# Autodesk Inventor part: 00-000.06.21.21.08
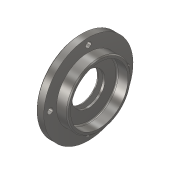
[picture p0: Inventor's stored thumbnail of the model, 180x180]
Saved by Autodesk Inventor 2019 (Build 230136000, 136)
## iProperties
Created: 2019-01
Part Number: 00-000.06.21.21.08
Material: Steel, Mild
Document SubType Name: Modeling
Designer: m.vorobev
Density: 7.85 g/cm^3
Appearance: Semi-Polished
Author: m.vorobev
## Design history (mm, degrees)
sketch "Sketch1"
  geometry: L1 (0, -26)-(12, -26); L2 (12, -26)-(12, -70); L3 (12, -70)-(0, -70); L4 (0, -70)-(0, -26); L5 (12, -50)-(29, -50); L6 (29, -50)-(29, -45); L7 (29, -45)-(12, -45); L8 (12, -45)-(12, -50); L9 (1.413, -26)-(8.5, -26); L10 (8.5, -26)-(7.456, -34.5); L11 (7.456, -34.5)-(2.456, -34.5); L12 (2.456, -34.5)-(1.413, -26); L13 (0, 0)-(11.392, 0); L14 (4.956, -34.5)-(4.956, -26); 1 further point
  constraints: 28 end point, 5 parallel, 4 horizontal, 3 midpoint, 2 perpendicular, 2 point on line, 1 vertical, 1 vertical alignment
  dimensions: "d0" = 140 diameter of L3 L13; "d1" = 100 diameter of L5 L13; "d2" = 90 diameter of L7 L13; "d3" = 52 diameter of L1 L13; "d4" = 5 distance of L10.end L11.end; "d5" = 14 deg angle of L10 L12; "d6" = 69 diameter of L11 L13; "d7" = 3.5 distance of L1.end L9.end; "d8" = 12 distance of L1.start L1.end; "B" = 29 distance between parallel lines of L4 L6
revolve "Revolution1" sketch "Sketch1" stored, may be unused: angle "d10" = 90 deg
fillet "Fillet1" dims "d11" = 2
chamfer "Chamfer1" distance "d12" = 1.5; stored, may be unused: second distance "d13" = 2, angle "d14" = 45 deg
sketch "Sketch2"
  geometry: L1 (0, 0)-(0, -60)
  constraints: 2 end point, 1 vertical
  dimensions: "d15" = 60 distance of L1.start L1.end
hole "Hole1" sketch "Sketch2" at (0, -60) diameter "d16" = 9; stored, may be unused: countersink angle "d20" = 90 deg, drill point angle "d22" = 118 deg; dims "d17" = 6, "d18" = 4, "d19" = 2, "d21" = 24
pattern_circular "Circular Pattern1" dims angle "d24" = 360 deg
body "Solid1"
